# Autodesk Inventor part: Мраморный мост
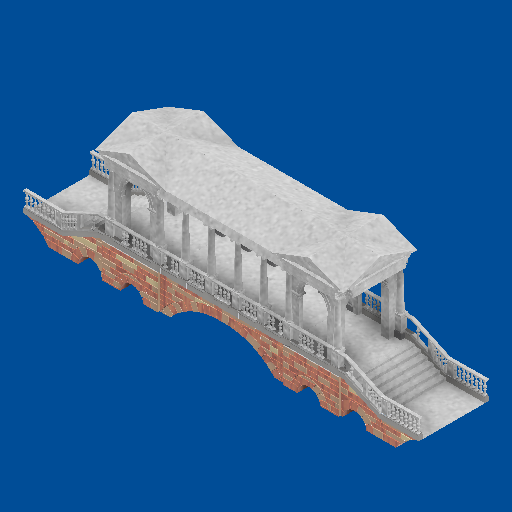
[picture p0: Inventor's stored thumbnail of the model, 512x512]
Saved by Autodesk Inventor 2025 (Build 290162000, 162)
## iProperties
Created: 2026-02
Part Number: Мраморный мост
Material: Типовые
Document SubType Name: Modeling
Designer: admin
Density: 1 g/cm^3
Appearance: Снег
Author: admin
## Parameters: d118 = 0.3 mm, d119 = 0.3 mm, d120 = 0.3 mm, d139 = 0, d146 = 4 mm, d147 = 0, d148 = 3.5 mm, d149 = 0, d150 = 0.5 mm, d151 = 0, d186 = 90 deg, d189 = 3.8 mm, d190 = 0, d191 = 4 mm, d192 = 0, d193 = 0.2 mm, d194 = 0, d195 = 90 deg, d198 = 4 mm, d199 = 0, d200 = 3.75 mm, d201 = 0, d202 = 0.25 mm, d203 = 0, d207 = 5 mm, d208 = 0, d209 = 2 mm, d210 = 0, d213 = 1.5 mm, d214 = 0, d217 = 1 mm, d218 = 0, d224 = 4 mm, d225 = 0, d226 = 2 mm, d227 = 0, d228 = 4 mm, d229 = 0, d233 = 90 deg, d234 = 90 deg, d235 = 4 mm, d236 = 0, d237 = 3.8 mm, d238 = 0, d239 = 0.2 mm, d240 = 0, d241 = 3.6 mm, d242 = 0, d247 = 0.3 mm, d248 = 0, d251 = 0.4 mm, d252 = 0, d253 = 0.6 mm, d254 = 0, d264 = 4 mm, d265 = 0, d266 = 4 mm, d267 = 0, d268 = 0, d269 = 0, d277 = 1.03007 mm, d279 = 1.5 mm, d280 = 0, d281 = 90 deg, d282 = 90 deg, d283 = 90 deg, d284 = 90 deg, d285 = 90 deg, d286 = 90 deg, d288 = 90 deg, d289 = 90 deg, d290 = 90 deg, d291 = 90 deg, d292 = 90 deg, d293 = 90 deg, d294 = 90 deg, d295 = 1.8 mm, d296 = 0, d297 = 1.8 mm, d298 = 0, d299 = 0.2 mm, d314 = 360 deg, d318 = 90 deg, d319 = 360 deg, d327 = 1.9 mm, d330 = 2.2 mm, d335 = 90 deg, d336 = 1.8 mm, d337 = 0, d338 = 0.2 mm, d339 = 1.5 mm, d340 = 0, d341 = 1.5 mm, d342 = 0, d345 = 1.5 mm, d346 = 0, d348 = 0, d350 = 0, d351 = 9.6 mm, d352 = 0, d360 = 10.6 mm, d361 = 0, d363 = 0, d365 = 0, d366 = 9.6 mm, d367 = 0, d368 = 10.6 mm, d369 = 0, d370 = 11 mm, d371 = 0, d372 = 0.1 mm, d373 = 0.1 mm, d374 = 11 mm, d375 = 0, d377 = 0, d378 = 0.1 mm, d379 = 0.1 mm, d380 = 0.1 mm, d381 = 0.06 mm, d382 = 0.06 mm, d383 = 0.1 mm, d384 = 0.1 mm, d385 = 0.1 mm, d386 = 0.1 mm, d387 = 11 mm, d388 = 0, d389 = 1.8 mm, d390 = 0, d391 = 0.2 mm, d392 = 0, d396 = 0, d397 = 1.6 mm, d398 = 0, d399 = 0.2 mm, d400 = 0, d401 = 0.2 mm, d402 = 0, d403 = 0.1 mm, d404 = 2 mm, d405 = 45 deg, d406 = 1.8 mm, d407 = 0, d408 = 0.2 mm, d409 = 2 mm, d410 = 45 deg, d412 = 0.5 mm, d413 = 0, d414 = 0.6 mm, d415 = 0, d416 = 0.7 mm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
